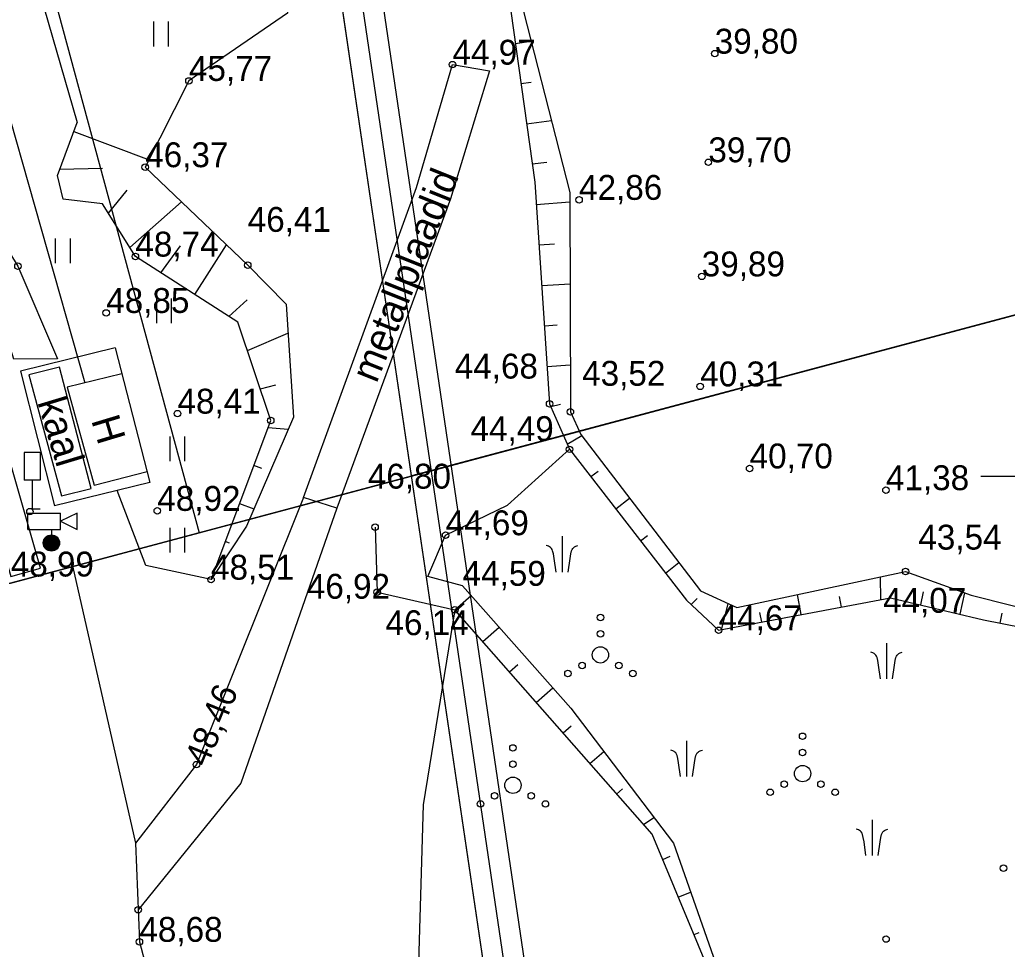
# Model space of a CAD drawing. Extents: x 700746 to 706058, y 6570320 to 6580460.
# Drawn here: x 702898.3 to 702995.6, y 6576853.4 to 6576945 of the extents above; entities that cross this region are included whole.
import ezdxf

# ---------------------------------------------------------------- set-up
doc = ezdxf.new("R2010")
doc.units = 0
for name, color, linetype in [('HALJASTUS', 7, 'Continuous'), ('HOONE', 7, 'Continuous'), ('illumineerimisjooned', 7, 'Continuous'), ('kataster', 7, 'Continuous'), ('KORGUS-EH2000', 7, 'Continuous'), ('KPKAABEL', 7, 'Continuous'), ('LIIKLUS', 7, 'Continuous'), ('Plokid', 7, 'Continuous'), ('POST', 7, 'Continuous'), ('RAJATIS', 7, 'Continuous'), ('RELJEEF', 7, 'Continuous'), ('TEE', 7, 'Continuous'), ('Tmaad_maeeraldised_kehtivad', 7, 'Continuous'), ('VEEKOGU', 7, 'Continuous'), ('VORK', 7, 'Continuous'), ('VWX2_MV_PLOKK', 7, 'Continuous')]:
    doc.layers.add(name, color=color, linetype=linetype)

msp = doc.modelspace()

# ---------------------------------------------------------------- linework, layer by layer
at = {"layer": 'HALJASTUS'}
for p, q in [((702911.467, 6576944.799), (702911.467, 6576942.364)), ((702912.923, 6576944.799), (702912.923, 6576942.364)), ((702901.781, 6576923.431), (702901.781, 6576920.996)), ((702903.237, 6576923.431), (702903.237, 6576920.996)), ((702911.743, 6576917.516), (702911.743, 6576915.08)), ((702913.2, 6576917.516), (702913.2, 6576915.08)), ((702913.057, 6576903.932), (702913.057, 6576901.497)), ((702914.513, 6576903.932), (702914.513, 6576901.497)), ((702913.057, 6576894.949), (702913.057, 6576892.514)), ((702914.513, 6576894.949), (702914.513, 6576892.514)), ((702951.731, 6576894.102), (702951.731, 6576890.578)), ((702983.7, 6576883.586), (702983.7, 6576880.062)), ((702963.993, 6576873.946), (702963.993, 6576870.422)), ((702982.276, 6576866.168), (702982.276, 6576862.644))]:
    msp.add_line(p, q, dxfattribs=at)
for points in [[(702917.133, 6576889.828), (702910.72, 6576891.209), (702907.882, 6576898.625)], [(702951.131, 6576890.578), (702950.942, 6576891.926), (702950.867, 6576892.377), (702950.799, 6576892.669), (702950.747, 6576892.8), (702950.673, 6576892.914), (702950.592, 6576892.997), (702950.504, 6576893.06), (702950.385, 6576893.121), (702950.282, 6576893.159), (702950.172, 6576893.191)], [(702952.331, 6576890.578), (702952.52, 6576891.926), (702952.596, 6576892.377), (702952.663, 6576892.669), (702952.715, 6576892.8), (702952.79, 6576892.914), (702952.871, 6576892.997), (702952.958, 6576893.06), (702953.077, 6576893.121), (702953.18, 6576893.159), (702953.29, 6576893.191)], [(702941.153, 6576886.856), (702938.026, 6576867.656), (702937.061, 6576834.256)], [(702983.1, 6576880.062), (702982.911, 6576881.409), (702982.836, 6576881.861), (702982.768, 6576882.152), (702982.716, 6576882.284), (702982.641, 6576882.397), (702982.56, 6576882.48), (702982.473, 6576882.544), (702982.354, 6576882.605), (702982.251, 6576882.643), (702982.141, 6576882.674)], [(702984.3, 6576880.062), (702984.489, 6576881.409), (702984.564, 6576881.861), (702984.632, 6576882.152), (702984.684, 6576882.284), (702984.758, 6576882.397), (702984.839, 6576882.48), (702984.927, 6576882.544), (702985.046, 6576882.605), (702985.149, 6576882.643), (702985.259, 6576882.674)], [(702963.393, 6576870.422), (702963.204, 6576871.769), (702963.129, 6576872.221), (702963.061, 6576872.512), (702963.009, 6576872.643), (702962.935, 6576872.757), (702962.854, 6576872.84), (702962.766, 6576872.904), (702962.647, 6576872.965), (702962.544, 6576873.003), (702962.434, 6576873.034)], [(702964.593, 6576870.422), (702964.782, 6576871.769), (702964.857, 6576872.221), (702964.925, 6576872.512), (702964.977, 6576872.643), (702965.052, 6576872.757), (702965.132, 6576872.84), (702965.22, 6576872.904), (702965.339, 6576872.965), (702965.442, 6576873.003), (702965.552, 6576873.034)], [(702981.676, 6576862.644), (702981.487, 6576863.992), (702981.412, 6576864.443), (702981.345, 6576864.735), (702981.293, 6576864.866), (702981.218, 6576864.979), (702981.137, 6576865.062), (702981.049, 6576865.126), (702980.93, 6576865.187), (702980.827, 6576865.225), (702980.718, 6576865.256)], [(702982.876, 6576862.644), (702983.066, 6576863.992), (702983.141, 6576864.443), (702983.208, 6576864.735), (702983.26, 6576864.866), (702983.335, 6576864.979), (702983.416, 6576865.062), (702983.503, 6576865.126), (702983.622, 6576865.187), (702983.726, 6576865.225), (702983.835, 6576865.256)]]:
    msp.add_lwpolyline(points, dxfattribs=at)
for centre, radius in [((702955.508, 6576886.097), 0.32), ((702955.508, 6576884.497), 0.32), ((702955.508, 6576882.417), 0.8), ((702953.7, 6576881.377), 0.32), ((702957.316, 6576881.377), 0.32), ((702952.308, 6576880.577), 0.32), ((702958.708, 6576880.577), 0.32), ((702975.434, 6576874.403), 0.32), ((702946.887, 6576873.253), 0.32), ((702975.434, 6576872.803), 0.32), ((702946.887, 6576871.653), 0.32), ((702975.434, 6576870.723), 0.8), ((702946.887, 6576869.573), 0.8), ((702973.626, 6576869.683), 0.32), ((702977.242, 6576869.683), 0.32), ((702972.234, 6576868.883), 0.32), ((702978.634, 6576868.883), 0.32), ((702943.687, 6576867.733), 0.32), ((702945.079, 6576868.533), 0.32), ((702948.695, 6576868.533), 0.32), ((702950.087, 6576867.733), 0.32), ((702995.225, 6576861.406), 0.32), ((702983.654, 6576854.426), 0.32)]:
    msp.add_circle(centre, radius, dxfattribs=at)
at = {"layer": 'HOONE'}
for p, q in [((702907.696, 6576912.653), (702898.351, 6576910.374)), ((702907.696, 6576912.653), (702911.114, 6576899.413)), ((702898.351, 6576910.374), (702901.697, 6576897.116)), ((702911.114, 6576899.413), (702901.697, 6576897.116))]:
    msp.add_line(p, q, dxfattribs=at)
msp.add_lwpolyline([(702908.355, 6576910.099), (702902.963, 6576908.784), (702905.611, 6576899.135), (702910.838, 6576900.484)], dxfattribs=at)
at = {"layer": 'illumineerimisjooned'}
msp.add_lwpolyline([(702976.891, 6576643.26), (702915.328, 6577059.558), (702785.772, 6577104.455), (702748.407, 6577249.47), (702721.642, 6577298.043), (702716.252, 6577332.033), (702861.102, 6577284.56), (703066.328, 6577217.365), (703088.858, 6577210.018), (703169.031, 6577150.466), (703230.271, 6577104.95), (703275.453, 6577071.675), (703358.033, 6576531.935)], dxfattribs=at)
at = {"layer": 'kataster'}
for points in [[(702852.27, 6575508.89), (702837.26, 6575620.73), (702848.38, 6575976.59), (702782.85, 6576063.35), (702782.57, 6576096.37), (702842.53, 6576210.56), (702853.4, 6576267.5), (702844.46, 6576489.93), (702877.29, 6576548.25), (702974.72, 6576643.9), (702913.57, 6577058.07), (702784.04, 6577102.84), (702746.48, 6577248.7), (702719.69, 6577297.36), (702713.81, 6577334.91), (703089.87, 6577211.79), (703231.53, 6577106.55), (703277.36, 6577072.83), (703360.09, 6576531.99), (703311.6, 6576228.52), (703293.62, 6575965.66), (703298.84, 6575573.29)], [(702723.93, 6577008.77), (702873.9, 6577049.58), (702915.96, 6576894.45), (702764.55, 6576854.07)]]:
    msp.add_lwpolyline(points, close=True, dxfattribs=at)
at = {"layer": 'KORGUS-EH2000'}
for centre in [(702966.774, 6576941.645), (702940.93, 6576940.561), (702914.956, 6576938.958), (702910.649, 6576930.459), (702966.143, 6576930.945), (702953.403, 6576927.244), (702909.679, 6576921.655), (702898.103, 6576920.718), (702920.75, 6576920.812), (702965.496, 6576919.706), (702906.804, 6576916.104), (702965.345, 6576908.869), (702950.501, 6576907.143), (702913.829, 6576906.184), (702952.546, 6576906.368), (702923.015, 6576905.5), (702952.461, 6576902.667), (702970.213, 6576900.786), (702983.648, 6576898.644), (702899.284, 6576896.528), (702911.839, 6576896.606), (702933.3, 6576895.003), (702940.255, 6576894.204), (702985.585, 6576890.639), (702917.133, 6576889.828), (702933.505, 6576888.6), (702941.153, 6576886.856), (702967.159, 6576884.838), (702915.708, 6576871.609), (702909.954, 6576857.319), (702910.073, 6576854.153)]:
    msp.add_circle(centre, 0.32, dxfattribs=at)
at = {"layer": 'KPKAABEL'}
msp.add_line((702886.213, 6576974.21), (702904.707, 6576909.22), dxfattribs=at)
at = {"layer": 'LIIKLUS'}
for p, q in [((702898.705, 6576902.365), (702898.705, 6576899.645)), ((702900.305, 6576902.365), (702898.705, 6576902.365)), ((702900.305, 6576902.365), (702900.305, 6576899.645)), ((702900.305, 6576899.645), (702898.705, 6576899.645)), ((702899.505, 6576899.645), (702899.505, 6576896.765)), ((702900.305, 6576896.765), (702899.505, 6576896.765))]:
    msp.add_line(p, q, dxfattribs=at)
at = {"layer": 'Plokid'}
msp.add_line((702936.9, 6576900.04), (703039.76, 6576927.49), dxfattribs=at)
for points in [[(702917.129, 6577061.05), (702979.018, 6576642.545), (702880.491, 6576545.858), (702848.554, 6576488.92), (702857.464, 6576267.152), (702846.343, 6576209.185), (702786.618, 6576095.345), (702786.772, 6576064.737), (702852.361, 6575977.948), (702841.238, 6575620.869), (702855.715, 6575513.483), (703019.069, 6575537.036)], [(702900.72, 6576571.25), (702840.26, 6576874.26), (702936.9, 6576900.04)]]:
    msp.add_lwpolyline(points, dxfattribs=at)
at = {"layer": 'POST'}
for p, q in [((702899.086, 6576896.384), (702902.286, 6576896.384)), ((702899.086, 6576894.784), (702899.086, 6576896.384)), ((702902.286, 6576894.784), (702902.286, 6576896.384)), ((702903.932, 6576896.384), (702902.286, 6576895.584)), ((702903.932, 6576894.784), (702903.932, 6576896.384)), ((702902.286, 6576895.584), (702903.932, 6576894.784)), ((702899.086, 6576894.784), (702902.286, 6576894.784)), ((702901.405, 6576894.784), (702901.405, 6576893.443))]:
    msp.add_line(p, q, dxfattribs=at)
for radius in [0.8, 0.72, 0.64, 0.56, 0.48, 0.4, 0.32, 0.24, 0.16, 0.08]:
    msp.add_circle((702901.405, 6576893.443), radius, dxfattribs=at)
at = {"layer": 'RAJATIS'}
for points in [[(702890.481, 6576914.258), (702897.397, 6576890.138), (702900.315, 6576890.963), (702893.384, 6576915.096)], [(702902.19, 6576910.747), (702899.187, 6576909.998), (702902.383, 6576898.076), (702905.329, 6576898.823)]]:
    msp.add_lwpolyline(points, close=True, dxfattribs=at)
at = {"layer": 'RELJEEF'}
for p, q in [((702947.121, 6576942.639), (702948.691, 6576942.86)), ((702948.682, 6576938.819), (702947.678, 6576938.678)), ((702948.235, 6576934.717), (702950.679, 6576935.061)), ((702903.615, 6576933.976), (702911.021, 6576931.193)), ((702906.439, 6576930.335), (702902.208, 6576930.232)), ((702950.24, 6576930.93), (702948.793, 6576930.756)), ((702908.83, 6576928.208), (702907.004, 6576925.944)), ((702909.121, 6576922.55), (702914.227, 6576927.042)), ((702949.19, 6576926.779), (702952.487, 6576927.053)), ((702914.077, 6576922.71), (702912.159, 6576920.066)), ((702915.527, 6576917.908), (702918.664, 6576922.804)), ((702950.978, 6576922.889), (702949.456, 6576922.788)), ((702949.723, 6576918.796), (702952.51, 6576918.983)), ((702920.68, 6576917.408), (702918.895, 6576915.75)), ((702951.255, 6576914.89), (702949.989, 6576914.805)), ((702920.715, 6576912.387), (702924.711, 6576914.12)), ((702950.256, 6576910.814), (702952.533, 6576910.998)), ((702923.5, 6576909), (702921.982, 6576908.593)), ((702951.586, 6576907.097), (702950.63, 6576906.849)), ((702922.755, 6576904.808), (702924.745, 6576904.651)), ((702952.234, 6576903.185), (702953.686, 6576904.014)), ((702922.144, 6576900.765), (702921.349, 6576901.063)), ((702955.271, 6576900.481), (702954.564, 6576899.952)), ((702919.944, 6576897.318), (702921.353, 6576896.79)), ((702957.014, 6576896.79), (702958.386, 6576897.853)), ((702918.969, 6576893.412), (702918.538, 6576893.573)), ((702960.138, 6576894.15), (702959.463, 6576893.628)), ((702961.913, 6576890.465), (702963.226, 6576891.509)), ((702917.133, 6576889.828), (702917.133, 6576889.828)), ((702983.156, 6576887.871), (702983.097, 6576890.107)), ((702987.298, 6576888.638), (702987.057, 6576887.34)), ((702990.949, 6576886.417), (702991.434, 6576888.537)), ((702941.153, 6576886.856), (702942.766, 6576888.274)), ((702965.046, 6576887.976), (702964.437, 6576887.371)), ((702975.296, 6576886.381), (702974.921, 6576888.358)), ((702979.03, 6576888.16), (702979.226, 6576887.126)), ((702942.07, 6576887.439), (702941.263, 6576886.73)), ((702967.436, 6576884.89), (702968.098, 6576887.463)), ((702971.187, 6576886.578), (702971.366, 6576885.636)), ((702995.057, 6576886.529), (702994.854, 6576885.554)), ((702943.904, 6576883.726), (702945.526, 6576885.152)), ((702947.36, 6576881.438), (702946.545, 6576880.721)), ((702949.185, 6576877.717), (702950.826, 6576879.159)), ((702952.614, 6576875.404), (702951.826, 6576874.712)), ((702954.467, 6576871.708), (702955.83, 6576872.906)), ((702957.684, 6576869.21), (702957.108, 6576868.704)), ((702959.748, 6576865.699), (702960.773, 6576866.415)), ((702962.342, 6576862.563), (702961.639, 6576862.227)), ((702963.179, 6576858.535), (702964.399, 6576859.043)), ((702965.222, 6576855.053), (702964.718, 6576854.843))]:
    msp.add_line(p, q, dxfattribs=at)
for points in [[(702739.023, 6577231.907), (702732.289, 6577216.851), (702732.578, 6577206.579), (702732.578, 6577206.579), (702734.587, 6577189.133), (702735.483, 6577169.869), (702735.843, 6577148.198), (702740.042, 6577134.132), (702751.77, 6577119.395), (702766.114, 6577109.288), (702803.835, 6577094.452), (702821.606, 6577090.674), (702840.938, 6577095.821), (702853.663, 6577093.094), (702862.518, 6577074.987), (702866.558, 6577057.669), (702873.986, 6577028.728), (702886.047, 6576996.678), (702903.946, 6576934.858)], [(702921.378, 6576967.998), (702929.09, 6576966.585), (702940.012, 6576965.981), (702944.031, 6576969.402), (702946.732, 6576976.629), (702968.04, 6576986.905), (702975.133, 6576984.344), (702976.568, 6576977.514), (702970.955, 6576971.57), (702961.177, 6576971.298), (702947.041, 6576960.841), (702942.299, 6576957.719), (702944.156, 6576950.5), (702946.139, 6576949.622), (702949.043, 6576928.975), (702950.501, 6576907.143), (702952.461, 6576902.667), (702963.982, 6576887.794), (702967.159, 6576884.838), (702984.08, 6576888.046), (702993.276, 6576885.865), (703006.615, 6576883.241)], [(702925.603, 6576961.204), (702924.662, 6576945.623), (702914.956, 6576938.958), (702910.649, 6576930.459), (702920.75, 6576920.812), (702924.525, 6576916.968), (702925.252, 6576905.826), (702920.621, 6576895.095), (702917.133, 6576889.828)], [(702917.133, 6576889.828), (702923.015, 6576905.5), (702919.783, 6576915.181), (702909.679, 6576921.655), (702906.445, 6576926.841), (702902.567, 6576927.306), (702901.986, 6576929.642), (702903.946, 6576934.858)], [(702941.927, 6576889.222), (702938.512, 6576890.153), (702940.255, 6576894.204), (702946.343, 6576897.161), (702952.461, 6576902.667)], [(702933.3, 6576895.003), (702933.505, 6576888.6), (702941.153, 6576886.856)], [(702941.927, 6576889.222), (702952.58, 6576877.174), (702962.7, 6576863.884), (702968.346, 6576847.794), (702964.895, 6576832.094), (702952.788, 6576825.8), (702947.599, 6576824.79), (702940.906, 6576827.962), (702940.136, 6576825.27), (702953.363, 6576818.74), (702948.565, 6576801.763), (702941.403, 6576781.638)], [(702965.057, 6576833.48), (702967.364, 6576848.497), (702960.591, 6576864.741), (702941.153, 6576886.856)]]:
    msp.add_lwpolyline(points, dxfattribs=at)
at = {"layer": 'TEE'}
for points in [[(702940.93, 6576940.561), (702944.566, 6576939.956), (702940.749, 6576927.342), (702929.524, 6576896.857), (702926.235, 6576897.93), (702937.397, 6576928.464), (702940.93, 6576940.561)], [(702889.525, 6576934.588), (702898.103, 6576920.718), (702902.008, 6576911.567), (702897.69, 6576911.548), (702896.314, 6576915.894)], [(702926.235, 6576897.93), (702915.708, 6576871.609), (702909.705, 6576863.884)], [(702929.524, 6576896.857), (702920.074, 6576869.776), (702909.954, 6576857.319)], [(702903.316, 6576891.918), (702909.705, 6576863.884), (702910.073, 6576854.153), (702913.534, 6576841.001), (702928.195, 6576787.245), (702933.993, 6576765.322)]]:
    msp.add_lwpolyline(points, dxfattribs=at)
at = {"layer": 'Tmaad_maeeraldised_kehtivad'}
msp.add_lwpolyline([(702974.764, 6576643.974), (702913.527, 6577058.065), (702784.103, 6577102.917), (702746.534, 6577248.726), (702719.722, 6577297.384), (702713.764, 6577334.953), (702861.724, 6577286.461), (703066.949, 6577219.266), (703089.789, 6577211.819), (703089.789, 6577211.819), (703170.224, 6577152.072), (703231.46, 6577106.558), (703277.305, 6577072.795), (703360.057, 6576531.928)], dxfattribs=at)
at = {"layer": 'VEEKOGU'}
msp.add_lwpolyline([(702946.884, 6576949.947), (702952.485, 6576927.981), (702952.546, 6576906.368), (702953.59, 6576904.141), (702965.354, 6576888.718), (702968.94, 6576887.078), (702985.585, 6576890.639), (702992.057, 6576888.313), (703007.819, 6576884.332)], dxfattribs=at)
msp.add_lwpolyline([(702946.884, 6576949.947), (702952.485, 6576927.981), (702952.546, 6576906.368), (702953.59, 6576904.141), (702965.354, 6576888.718), (702968.94, 6576887.078), (702985.585, 6576890.639), (702992.057, 6576888.313), (703007.819, 6576884.332)], dxfattribs=at)
at = {"layer": 'VORK'}
msp.add_line((703000, 6576900), (702993, 6576900), dxfattribs=at)
msp.add_line((703000, 6576900), (702993, 6576900), dxfattribs=at)
at = {"layer": 'VWX2_MV_PLOKK'}
for points in [[(703039.76, 6576927.49), (702936.9, 6576900.04), (702913.57, 6577058.07), (702968.34, 6577084.63), (703011.59, 6576989.47)], [(703039.76, 6576927.49), (702936.9, 6576900.04), (702913.57, 6577058.07), (702968.34, 6577084.63), (703011.59, 6576989.47)], [(702840.26, 6576874.26), (702915.96, 6576894.45), (703039.76, 6576927.49), (703072.13, 6576856.26), (703101.31, 6576579.97), (703076.01, 6576303.02), (703067.36, 6576229.67), (702842.72, 6576158.42), (702853.4, 6576267.5), (702860.12, 6576517.75), (702877.29, 6576548.25), (702900.72, 6576571.25)], [(702840.26, 6576874.26), (702915.96, 6576894.45), (703039.76, 6576927.49), (703072.13, 6576856.26), (703101.31, 6576579.97), (703076.01, 6576303.02), (703067.36, 6576229.67), (702842.72, 6576158.42), (702853.4, 6576267.5), (702860.12, 6576517.75), (702877.29, 6576548.25), (702900.72, 6576571.25)]]:
    msp.add_lwpolyline(points, close=True, dxfattribs=at)

# ---------------------------------------------------------------- texts
at = {"layer": 'HOONE'}
msp.add_text('H', height=2.8, rotation=286.80511, dxfattribs=at).set_placement((702905.304, 6576905.545))
at = {"layer": 'KORGUS-EH2000'}
for s, p in [('39,80 ', (702966.774, 6576941.645)), ('44,97 ', (702940.93, 6576940.561)), ('45,77 ', (702914.956, 6576938.958)), ('39,70 ', (702966.143, 6576930.945)), ('46,37 ', (702910.649, 6576930.459)), ('42,86 ', (702953.403, 6576927.244)), ('46,41 ', (702920.75, 6576924.092)), ('48,74 ', (702909.679, 6576921.655)), ('39,89 ', (702965.496, 6576919.706)), ('48,85 ', (702906.804, 6576916.104)), ('44,68 ', (702941.152, 6576909.638)), ('43,52 ', (702953.707, 6576908.93)), ('40,31 ', (702965.345, 6576908.869)), ('48,41 ', (702913.829, 6576906.184)), ('44,49 ', (702942.711, 6576903.483)), ('40,70 ', (702970.213, 6576900.786)), ('46,80 ', (702932.583, 6576898.796)), ('41,38 ', (702983.648, 6576898.644)), ('48,92 ', (702911.839, 6576896.606)), ('44,69 ', (702940.255, 6576894.204)), ('43,54 ', (702986.84, 6576892.791)), ('48,99 ', (702897.397, 6576890.138)), ('48,51 ', (702917.133, 6576889.828)), ('44,59 ', (702941.927, 6576889.222)), ('46,92 ', (702926.573, 6576887.951)), ('44,07 ', (702983.363, 6576886.568)), ('46,14 ', (702934.323, 6576884.362)), ('44,67 ', (702967.159, 6576884.838)), ('48,68 ', (702910.073, 6576854.153))]:
    msp.add_text(s, height=2.45, dxfattribs=at).set_placement(p)
msp.add_text('48,46 ', height=2.45, rotation=67.67144, dxfattribs=at).set_placement((702916.73, 6576871.278))
at = {"layer": 'RAJATIS'}
msp.add_text('kaal', height=2.8, rotation=286.80511, dxfattribs=at).set_placement((702900, 6576907.332))
at = {"layer": 'TEE'}
msp.add_text('metallplaadid', height=2.8, rotation=68.27143, dxfattribs=at).set_placement((702933.441, 6576909.093))

doc.saveas('drawing.dxf')
